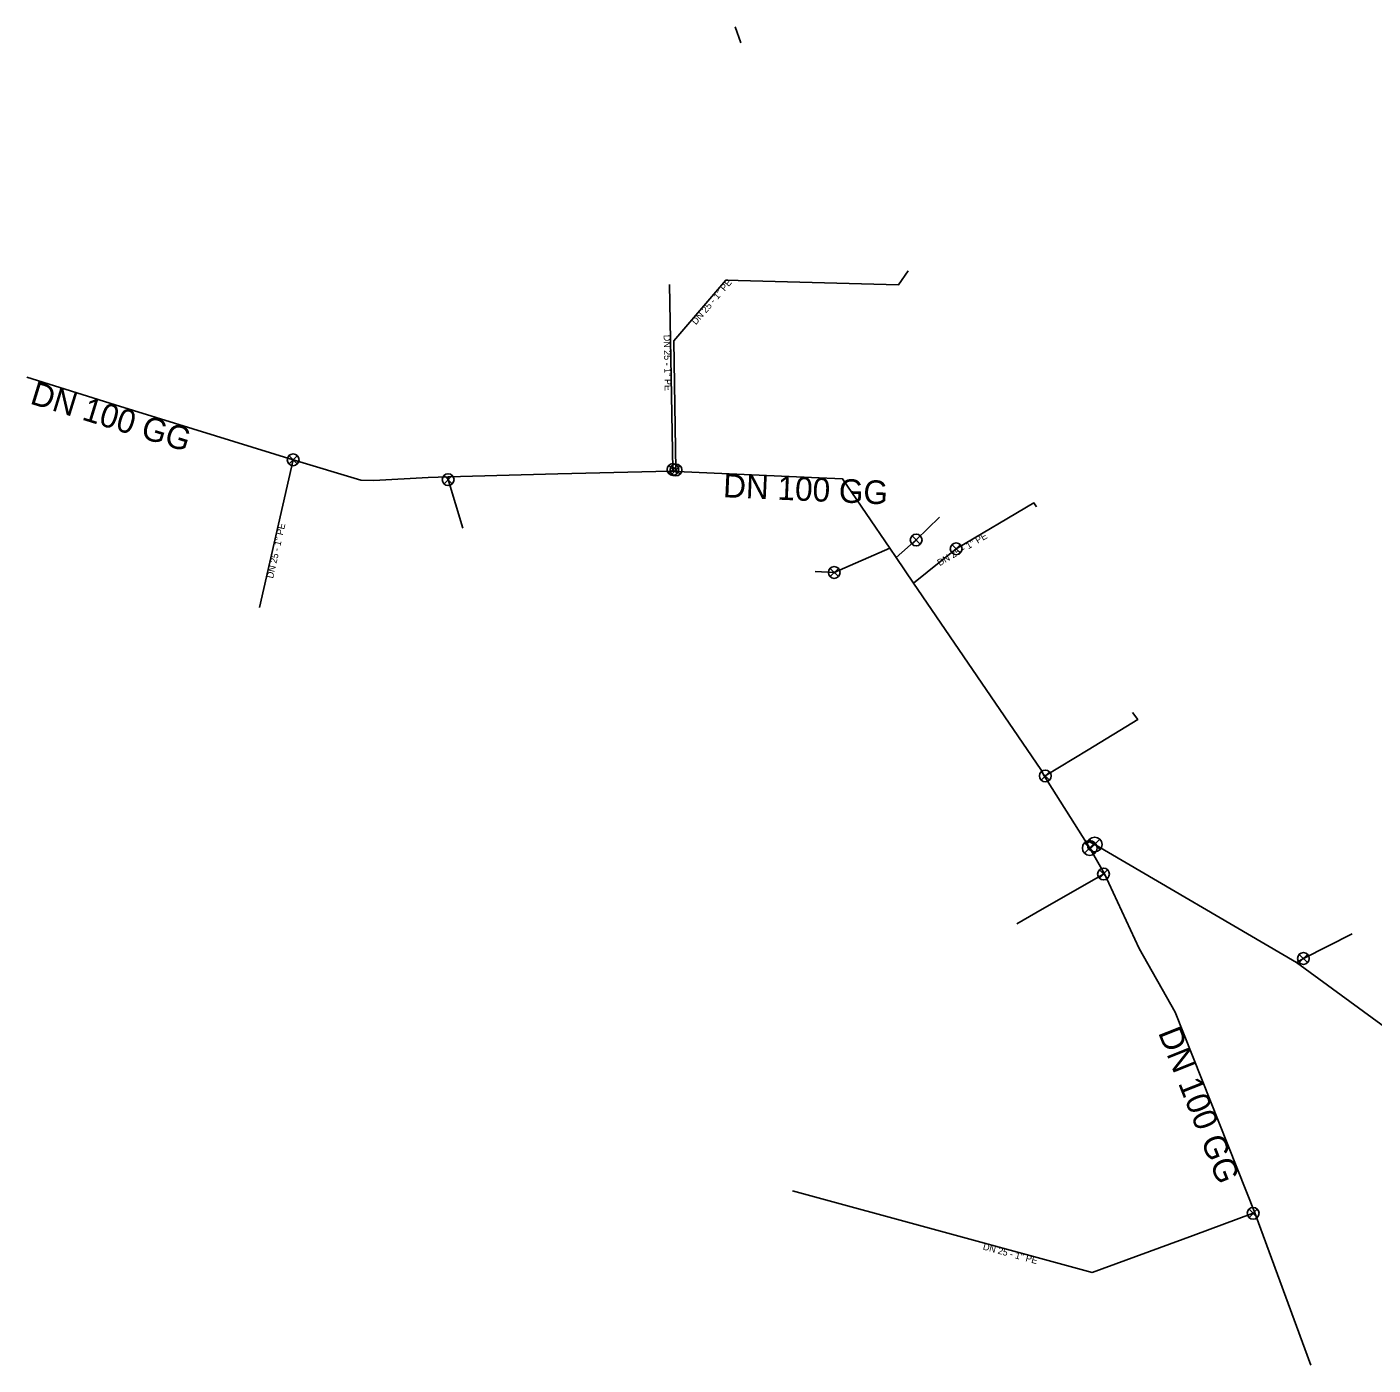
# Model space of a CAD drawing. Extents: x -484785 to -484462, y -1128039 to -1127627.
# Drawn here: x -484784.7 to -484693.2, y -1127718.2 to -1127627.3 of the extents above; entities that cross this region are included whole.
import ezdxf

# ---------------------------------------------------------------- set-up
doc = ezdxf.new("R2010")
doc.units = 0
for name, color, linetype in [('_pripojka_prevzato_z_dokumentace_', 7, 'Continuous'), ('_pripojka_priblizne_', 7, 'Continuous'), ('_voda_smvak_prevzato_z_dokumentace_', 7, 'Continuous'), ('Default', 7, 'Continuous'), ('MoLevel 27', 7, 'Continuous'), ('MoLevel 32', 7, 'Continuous'), ('MoLevel 46', 7, 'Continuous'), ('MoLevel 53', 7, 'Continuous'), ('MoLevel 55', 7, 'Continuous')]:
    doc.layers.add(name, color=color, linetype=linetype)

# ---------------------------------------------------------------- blocks, each defined once
blk = doc.blocks.new('_uzaver_')
at = {"layer": 'Default'}
for p, q in [((-0.000035, -0.000035), (0.000035, 0.000035)), ((0.000035, -0.000035), (-0.000035, 0.000035))]:
    blk.add_line(p, q, dxfattribs=at)
for radius in [0.00005, 0.0000025]:
    blk.add_circle((0, 0), radius, dxfattribs=at)
blk = doc.blocks.new('_uzaver_pripojka_')
at = {"layer": 'Default'}
for p, q in [((-0.000035, -0.000035), (0.000035, 0.000035)), ((0.000035, -0.000035), (-0.000035, 0.000035))]:
    blk.add_line(p, q, dxfattribs=at)
for radius in [0.00005, 0.0000025]:
    blk.add_circle((0, 0), radius, dxfattribs=at)

msp = doc.modelspace()

# ---------------------------------------------------------------- linework, layer by layer
at = {"layer": '_pripojka_prevzato_z_dokumentace_'}
for p, q in [((-484768.878, -1127666.751), (-484766.6, -1127656.71)), ((-484715.674, -1127687.26), (-484717.397, -1127688.246))]:
    msp.add_line(p, q, dxfattribs=at)
for points in [[(-484756.056, -1127657.875), (-484756.06, -1127658.06), (-484755.059, -1127661.369)], [(-484725.603, -1127663.357), (-484724.24, -1127662.16), (-484722.649, -1127660.607)], [(-484731.109, -1127664.308), (-484729.81, -1127664.37), (-484726.036, -1127662.721)], [(-484711.434, -1127684.862), (-484711.5, -1127684.87), (-484715.674, -1127687.26)], [(-484698.386, -1127690.884), (-484697.91, -1127690.61), (-484694.591, -1127688.939)]]:
    msp.add_lwpolyline(points, dxfattribs=at)
at = {"layer": '_pripojka_priblizne_'}
for p, q in [((-484736.547, -1127627.284), (-484736.157, -1127628.366)), ((-484724.413, -1127665.103), (-484721.52, -1127662.76))]:
    msp.add_line(p, q, dxfattribs=at)
for points in [[(-484740.515, -1127657.506), (-484740.57, -1127657.4), (-484740.721, -1127648.626), (-484737.19, -1127644.502), (-484725.437, -1127644.811), (-484724.793, -1127643.858)], [(-484740.789, -1127657.492), (-484740.78, -1127657.37), (-484741.016, -1127644.794)], [(-484721.52, -1127662.76), (-484716.233, -1127659.642), (-484716.059, -1127659.902)], [(-484712.549, -1127676.419), (-484709.176, -1127674.357), (-484709.521, -1127673.882)], [(-484715.528, -1127678.193), (-484715.46, -1127678.2), (-484712.549, -1127676.419)], [(-484705.418, -1127709.431), (-484712.273, -1127711.948), (-484732.652, -1127706.413)], [(-484701.224, -1127707.897), (-484701.33, -1127707.93), (-484705.418, -1127709.431)]]:
    msp.add_lwpolyline(points, dxfattribs=at)
at = {"layer": '_voda_smvak_prevzato_z_dokumentace_'}
msp.add_line((-484712.44, -1127683.106), (-484712.65, -1127682.74), dxfattribs=at)
for points in [[(-484761.112, -1127658.109), (-484762.003, -1127658.086), (-484766.6, -1127656.71), (-484778.69, -1127652.98), (-484784.699, -1127651.093)], [(-484712.65, -1127682.74), (-484715.528, -1127678.193), (-484715.774, -1127677.758), (-484724.413, -1127665.103), (-484725.603, -1127663.357), (-484726.036, -1127662.721), (-484729.244, -1127658.008), (-484731.355, -1127657.914), (-484740.515, -1127657.506), (-484740.789, -1127657.492), (-484740.995, -1127657.484), (-484748.599, -1127657.663), (-484756.056, -1127657.875), (-484757.408, -1127657.914), (-484761.112, -1127658.109)], [(-484712.097, -1127682.86), (-484712.46, -1127682.676), (-484712.65, -1127682.74)], [(-484643.08, -1127765.34), (-484645.558, -1127761.377), (-484646.121, -1127760.523), (-484650.612, -1127753.602), (-484650.955, -1127753.108), (-484652.744, -1127750.288), (-484654.582, -1127747.805), (-484659.496, -1127741.98), (-484663.295, -1127738.246), (-484667.445, -1127734.471), (-484668.218, -1127733.675), (-484673.26, -1127728.099), (-484673.76, -1127727.546), (-484675.038, -1127726.215), (-484681.24, -1127716.168), (-484682.755, -1127712.65), (-484683.576, -1127711.276), (-484684.331, -1127709.732), (-484687.857, -1127701.916), (-484687.921, -1127701.756), (-484691.708, -1127695.751), (-484698.386, -1127690.884), (-484712.097, -1127682.86)], [(-484697.4, -1127718.25), (-484701.224, -1127707.897), (-484706.631, -1127694.259), (-484709.079, -1127689.93), (-484711.434, -1127684.862), (-484712.44, -1127683.106)]]:
    msp.add_lwpolyline(points, dxfattribs=at)

# ---------------------------------------------------------------- block references
at = {"layer": 'MoLevel 27', "xscale": 10000, "yscale": 10000}
for p in [(-484712.44, -1127683.106), (-484712.097, -1127682.86)]:
    msp.add_blockref('_uzaver_', p, dxfattribs=at)
at = {"layer": 'MoLevel 53', "xscale": 7999.999999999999, "yscale": 7999.999999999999}
for p in [(-484766.6, -1127656.71), (-484740.78, -1127657.37), (-484740.57, -1127657.4), (-484756.06, -1127658.06), (-484724.24, -1127662.16), (-484721.52, -1127662.76), (-484729.81, -1127664.37), (-484715.46, -1127678.2), (-484711.5, -1127684.87), (-484697.91, -1127690.61), (-484701.33, -1127707.93)]:
    msp.add_blockref('_uzaver_pripojka_', p, dxfattribs=at)

# ---------------------------------------------------------------- texts
at = {"layer": 'MoLevel 32'}
for rotation, p in [(49.42961, (-484739.214, -1127647.566)), (271.07508, (-484741.407, -1127648.216)), (30.52991, (-484722.643, -1127663.95)), (344.80485, (-484719.736, -1127710.392))]:
    msp.add_text("DN 25 - 1'' PE", height=0.455, rotation=rotation, dxfattribs=at).set_placement(p)
at = {"layer": 'MoLevel 46'}
for rotation, p in [(342.85539, (-484784.559, -1127652.874)), (357.45038, (-484737.39, -1127659.252)), (291.62663, (-484707.808, -1127695.645))]:
    msp.add_text('DN 100 GG', height=1.6049, rotation=rotation, dxfattribs=at).set_placement(p)
at = {"layer": 'MoLevel 55'}
msp.add_text("DN 25 - 1'' PE", height=0.455, rotation=77.21769, dxfattribs=at).set_placement((-484767.965, -1127664.801))

doc.saveas('drawing.dxf')
